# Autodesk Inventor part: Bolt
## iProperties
Shininess: 77.0
Length Units: 11269
Angle Units: 11279
Time Units: 11290
Mass Units: 11283
Length Display Precision: 3
Angle Display Precision: 2
Created: 2002-02
Part Number: Bolt
Document SubType Name: Modeling
Designer: ***
Description: CADSoft's Bolt
Density: 0.0
Volumn: 0.0
Area: 0.0
PropertySet Name: Model Information
Control State: 0
Master: False
Checked Out: False
Author: ***
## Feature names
1. Extrusion1
2. Fillet1
3. Extrusion2
4. Extrusion3
